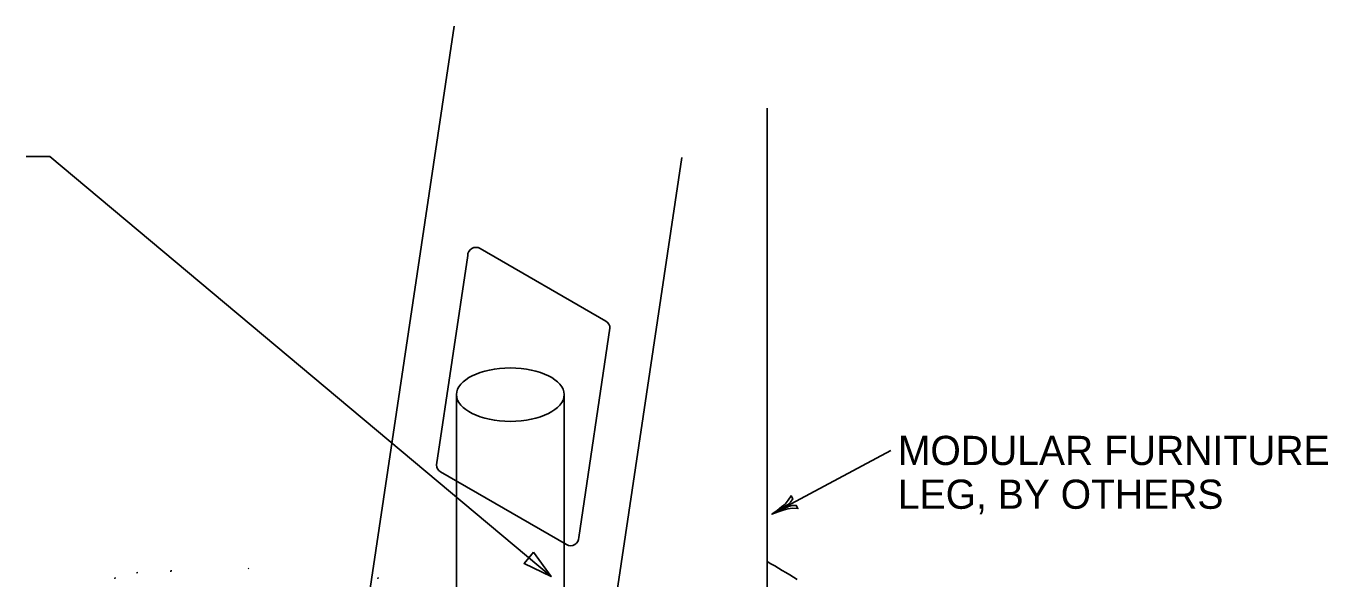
# Model space of a CAD drawing. Extents: x 10309.1 to 10402.7, y 9934 to 9975.2.
# Drawn here: x 10373.63 to 10400.38, y 9963.79 to 9975.15 of the extents above; entities that cross this region are included whole.
import ezdxf

# ---------------------------------------------------------------- set-up
doc = ezdxf.new("R2010")
doc.units = 0
for name, color, linetype in [('G-ANNO-TEXT', 7, 'Continuous'), ('G-DETL-LINE', 7, 'Continuous'), ('G-DETL-OTLN', 7, 'Continuous'), ('G-DETL-PATT', 7, 'Continuous')]:
    doc.layers.add(name, color=color, linetype=linetype)

msp = doc.modelspace()

# ---------------------------------------------------------------- linework, layer by layer
at = {"layer": 'G-ANNO-TEXT'}
for p, q in [((10373.631, 9972.468), (10374.118, 9972.468)), ((10374.118, 9972.468), (10384.419, 9963.835)), ((10391.4, 9966.424), (10388.956, 9965.117))]:
    msp.add_line(p, q, dxfattribs=at)
msp.add_lwpolyline([(10389.022, 9965.153), (10389.295, 9965.278), (10389.37, 9965.296), (10389.454, 9965.299), (10389.49, 9965.233), (10389.38, 9965.238), (10389.28, 9965.227), (10389.189, 9965.199), (10389.081, 9965.163), (10388.956, 9965.117), (10389.063, 9965.196), (10389.153, 9965.265), (10389.227, 9965.326), (10389.292, 9965.403), (10389.348, 9965.497), (10389.384, 9965.431), (10389.335, 9965.363), (10389.278, 9965.311), (10389.022, 9965.153)], dxfattribs=at)
msp.add_lwpolyline([(10384.055, 9964.336), (10384.419, 9963.835), (10383.863, 9964.106)], close=True, dxfattribs=at)
at = {"layer": 'G-DETL-LINE'}
for p, q in [((10382.476, 9967.587), (10382.476, 9958.613)), ((10384.685, 9967.578), (10384.685, 9958.225))]:
    msp.add_line(p, q, dxfattribs=at)
msp.add_ellipse((10383.581, 9967.574), major_axis=(1.105, 0), ratio=0.497156, dxfattribs=at)
at = {"layer": 'G-DETL-OTLN'}
for p, q in [((10375.93, 9963.919), (10375.901, 9963.913)), ((10376.603, 9963.934), (10376.612, 9963.963)), ((10378.208, 9963.994), (10378.194, 9964.008)), ((10375.456, 9963.791), (10375.465, 9963.819)), ((10380.856, 9963.791), (10380.865, 9963.819))]:
    msp.add_line(p, q, dxfattribs=at)
at = {"layer": 'G-DETL-PATT'}
for p, q in [((10382.425, 9975.152), (10380.46, 9961.961)), ((10388.856, 9961.771), (10388.856, 9973.464)), ((10387.102, 9972.452), (10385.191, 9959.625)), ((10382.705, 9970.433), (10382.064, 9966.131)), ((10385.543, 9969.087), (10382.958, 9970.58)), ((10385.628, 9968.941), (10384.986, 9964.638)), ((10384.733, 9964.492), (10382.148, 9965.985))]:
    msp.add_line(p, q, dxfattribs=at)
for centre, radius, start, end in [((10382.873, 9970.433), 0.169, 60, 180), ((10385.459, 9968.941), 0.169, 0, 60), ((10382.232, 9966.131), 0.169, 180, 240), ((10384.818, 9964.638), 0.169, 240, 0), ((10383.281, 9954.197), 11.402, 57.1162, 60.7338)]:
    msp.add_arc(centre, radius, start, end, dxfattribs=at)

# ---------------------------------------------------------------- texts
at = {"layer": 'G-ANNO-TEXT'}
for s, p in [('MODULAR FURNITURE', (10391.543, 9966.128)), ('LEG, BY OTHERS', (10391.543, 9965.228))]:
    msp.add_text(s, height=0.6, dxfattribs=at).set_placement(p)

doc.saveas('drawing.dxf')
